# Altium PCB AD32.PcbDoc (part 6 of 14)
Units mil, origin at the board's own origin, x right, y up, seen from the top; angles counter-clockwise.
Board outline 7007.87 x 4368.85 mil, 12 copper layers (Top Layer, Int1 (GND), Int2 (AVDD), Int3 (DVDD), Int4 (GND), Int5 (ST), Int6 (SB), Int8 (AGND), Int7 (AVCC), Int9 (VCCA), Int10 (GND), Bottom Layer), stack 60.136 mil thick; 1350 components, 880 nets, 4712 pads, 2835 vias.
Unrouted connection lines stored in the file: 19.
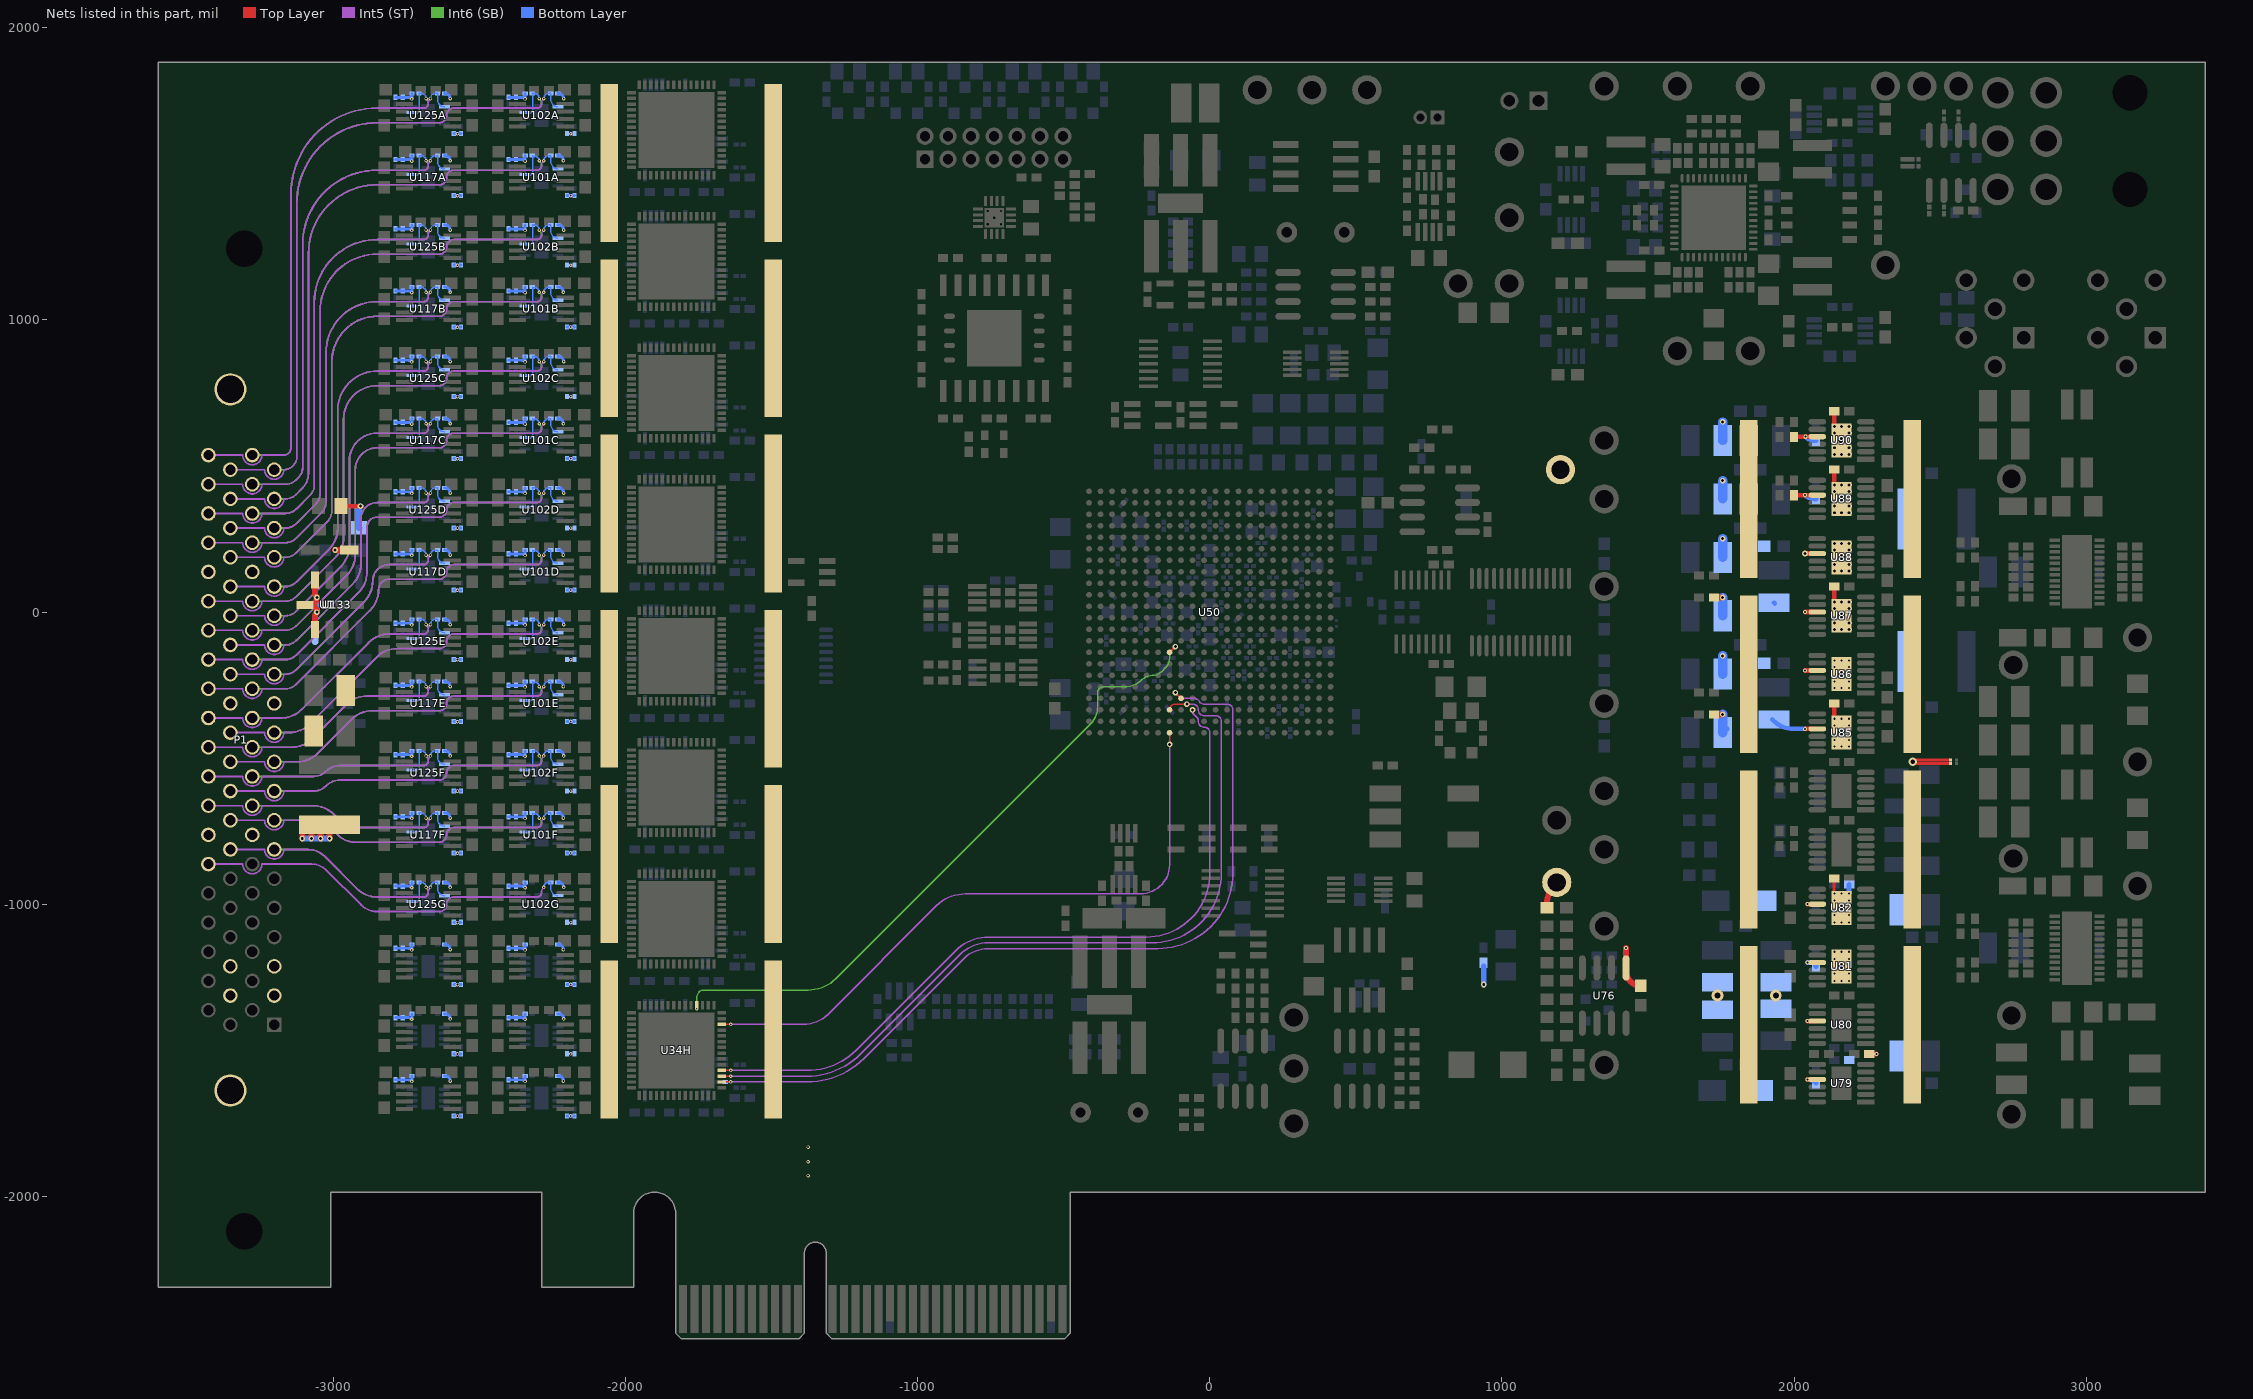
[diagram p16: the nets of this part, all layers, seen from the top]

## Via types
v1: diameter 12, hole 6, Top Layer to Bottom Layer, tented both sides, 1497 vias
v2: diameter 20, hole 10, Top Layer to Bottom Layer, tented both sides, 364 vias
v3: diameter 19, hole 10, Top Layer to Bottom Layer, tented both sides, 347 vias
v4: diameter 14, hole 7, Top Layer to Bottom Layer, tented both sides, 228 vias
v5: diameter 19.68, hole 7.87, Top Layer to Bottom Layer, 225 vias
v6: diameter 19.02, hole 10, Top Layer to Bottom Layer, tented both sides, 85 vias
v7: diameter 20, hole 10, Top Layer to Bottom Layer, 32 vias
v8: diameter 40, hole 20, Top Layer to Bottom Layer, tented both sides, 14 vias
v9: diameter 30, hole 15, Top Layer to Bottom Layer, tented both sides, 12 vias
v10: diameter 25, hole 13, Top Layer to Bottom Layer, 8 vias
v11: diameter 40, hole 20, Top Layer to Bottom Layer, 6 vias
v12: diameter 50, hole 20, Top Layer to Bottom Layer, 6 vias
v13: diameter 66, hole 47, Top Layer to Bottom Layer, tented both sides, 3 vias
v14: diameter 63, hole 45, Top Layer to Bottom Layer, 2 vias
v15: diameter 50, hole 25, Top Layer to Bottom Layer, 2 vias
v16: diameter 12, hole 6, Top Layer to Bottom Layer, 2 vias
v17: diameter 60, hole 40, Top Layer to Bottom Layer, tented both sides, 1 vias
v18: diameter 60, hole 40, Top Layer to Bottom Layer, 1 vias

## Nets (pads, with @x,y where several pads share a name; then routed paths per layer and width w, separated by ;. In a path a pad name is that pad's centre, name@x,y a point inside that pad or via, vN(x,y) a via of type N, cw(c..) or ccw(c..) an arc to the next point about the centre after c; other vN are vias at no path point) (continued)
ADC8.GPIO7: U34H.18 U50.H15 | length 2258.9
  Top Layer w5: U50.H15@-137.8,-137.8 v6(-118.11,-118.11)
  Int6 (SB) w5: v1(-1756.1,-1357.31) -1756.1,-1318.6 cw(c-1731.25,-1318.6) -1731.25,-1293.75 -1374.54,-1293.75 ccw(c-1374.54,-1160.15) -1280.07,-1254.62 -409.51,-384.06 ccw(c-471.45,-322.12) -383.86,-322.12 -383.86,-275.59 cw(c-364.17,-275.59) -364.17,-255.91 -291.9,-255.91 ccw(c-291.9,-169.01) -230.45,-230.45 cw(c-196.85,-264.06) -196.85,-216.54 ccw(c-196.85,-169.01) -163.25,-202.62 -151.71,-191.08 ccw(c-185.32,-157.48) -137.8,-157.48 cw(c-90.27,-157.48) v6@-123.89,-123.89 ; v6@-123.88,-123.88 v6(-118.11,-118.11)
ADC8.ODR: U34H.12 U50.A15 | length 2214.8
  Top Layer w5: U34H.12@-1670.38,-1411.42 v1(-1639.57,-1411.42) ; v6(-137.8,-452.76) U50.A15@-137.8,-413.39
  Int5 (ST) w5: v1(-1639.57,-1411.42) -1391.38,-1411.42 ccw(c-1391.38,-1291.73) -1306.75,-1376.36 -935.77,-1005.39 cw(c-837.22,-1103.94) -837.22,-964.57 -237.8,-964.57 ccw(c-237.8,-864.57) -137.8,-864.57 v6(-137.8,-452.76)
ADC8.SCLK: R417H.1 U34H.2 U50.D14 | length 2895.7
  Top Layer w5: U34H.2@-1670.38,-1608.27 v1(-1639.57,-1608.27) ; v6(-118.11,-275.59) U50.D14@-98.43,-295.28
  Int5 (ST) w5: v1(-1639.57,-1608.27) -1378.87,-1608.27 ccw(c-1378.87,-1331.1) -1182.88,-1527.09 -842.42,-1186.63 cw(c-757.79,-1271.26) -757.79,-1151.57 -178.74,-1151.57 ccw(c-178.74,-894.09) 78.74,-894.09 78.74,-334.65 ccw(c59.06,-334.65) 59.06,-314.96 -19.68,-314.96 cw(c-19.68,-295.28) -36.73,-305.12 ccw(c-53.78,-314.96) -53.78,-295.28 -78.74,-295.28 cw(c-78.74,-247.75) -112.34,-281.37 v6(-118.11,-275.59)
  Bottom Layer w5: R417H.1@-1658.44,-1608.27 v1(-1639.57,-1608.27)
ADC8.SI: U34H.4 U50.C13 | length 2555.9
  Top Layer w5: U34H.4@-1670.38,-1568.9 v1@-1639.53,-1568.9
  Int5 (ST) w5: v1(-1639.57,-1568.9) -1378.87,-1568.9 ccw(c-1378.87,-1331.1) -1210.72,-1499.25 -870.26,-1158.79 cw(c-757.79,-1271.26) -757.79,-1112.2 -218.11,-1112.2 ccw(c-218.11,-894.09) 0,-894.09 0,-413.39 ccw(c-19.68,-413.39) -19.68,-393.7 cw(c-19.68,-374.02) -39.37,-374.02 -39.37,-371.71 ccw(c-52.81,-371.71) -43.31,-362.2 -55.12,-350.39 cw(c-45.61,-340.89) -59.06,-340.89 v6(-59.06,-334.65)
ADC8.SO: U34H.3 U50.C15 | length 2759.8
  Top Layer w5: U34H.3@-1670.38,-1588.58 v1(-1639.57,-1588.58) ; U50.C15@-137.8,-334.65 cw(c-118.11,-334.65) -118.11,-314.96 v6(-78.74,-314.96)
  Int5 (ST) w5: v1(-1639.57,-1588.58) -1378.86,-1588.58 ccw(c-1378.86,-1331.1) -1196.8,-1513.17 -856.34,-1172.71 cw(c-757.79,-1271.26) -757.79,-1131.89 -198.43,-1131.89 ccw(c-198.43,-894.09) 39.37,-894.09 39.37,-374.02 ccw(c19.69,-374.02) 19.69,-354.33 -19.69,-354.33 cw(c-19.69,-334.65) -39.37,-334.65 ccw(c-59.06,-334.65) -59.06,-314.96 v6(-78.74,-314.96)
AGND: C1.1 C2.1 C7.2 C8.2 C63.1 C67.1 C80.1 C81.1 C108.1 C109.2 C112.2 C113.1 C120.2 C121.1 C122.1 C123.1 C128.2 C129.1 C130.1 C131.1 C132.1 C133.1 C134.1 C135.1 C145.1 C384A.1 C384B.1 C384C.1 C384D.1 C384E.1 C384F.1 C384G.1 C384H.1 C385A.1 C385B.1 C385C.1 C385D.1 C385E.1 C385F.1 C385G.1 C385H.1 C400A.2 C400B.2 C400C.2 C400D.2 C400E.2 C400F.2 C400G.2 C400H.2 C401A.2 C401B.2 C401C.2 C401D.2 C401E.2 C401F.2 C401G.2 C401H.2 C416A.1 C416B.1 C416C.1 C416D.1 C416E.1 C416F.1 C416G.1 C416H.1 C424A.1 C424B.1 C424C.1 C424D.1 C424E.1 C424F.1 C424G.1 C424H.1 C432A.2 C432B.2 C432C.2 C432D.2 C432E.2 C432F.2 C432G.2 C432H.2 C440A.2 C440B.2 C440C.2 C440D.2 C440E.2 C440F.2 C440G.2 C440H.2 C448A.1 C448B.1 C448C.1 C448D.1 C448E.1 C448F.1 C448G.1 C448H.1 C449A.1 C449B.1 C449C.1 C449D.1 C449E.1 C449F.1 C449G.1 C449H.1 C464A.2 C464B.2 C464C.2 C464D.2 C464E.2 C464F.2 C464G.2 C464H.2 C465A.2 C465B.2 C465C.2 C465D.2 C465E.2 C465F.2 C465G.2 C465H.2 C480A.2 C480B.2 C480C.2 C480D.2 C480E.2 C480F.2 C480G.2 C480H.2 C488A.1 C488B.1 C488C.1 C488D.1 C488E.1 C488F.1 C488G.1 C488H.1 C496A.1 C496B.1 C496C.1 C496D.1 C496E.1 C496F.1 C496G.1 C496H.1 C504A.2 C504B.2 C504C.2 C504D.2 C504E.2 C504F.2 C504G.2 C504H.2 C512.2 D3.1 D9.1 D10.2 MP1.1 MP1.2 MP2.1 MP2.2 MP3.1 MP3.2 MP4.1 MP4.2 MP5.1 MP5.2 MP6.1 MP6.2 MP7.1 MP7.2 MP8.1 MP8.2 MP9.1 MP9.2 MP10.1 MP10.2 P1.5 P1.6 P1.9 P1.10 P1.27 P1.28 P1.45 P1.46 P1.63 P1.64 P1.81 P1.82 R220.2 R222.2 R231.2 R232.1 R247.2 R248.2 R249.2 R250.2 R252.1 R257.1 R305.2 R307.2 R309.2 R310.1 R312.1 R313.1 R316.2 R317.2 R553A.2 R553B.2 R553C.2 R553D.2 R553E.2 R553F.2 R553G.2 R553H.2 R554A.2 R554B.2 R554C.2 R554D.2 R554E.2 R554F.2 R554G.2 R554H.2 R569A.1 R569B.1 R569C.1 R569D.1 R569E.1 R569F.1 R569G.1 R569H.1 R577A.1 R577B.1 R577C.1 R577D.1 R577E.1 R577F.1 R577G.1 R577H.1 R617A.2 R617B.2 R617C.2 R617D.2 R617E.2 R617F.2 R617G.2 R617H.2 R618A.2 R618B.2 R618C.2 R618D.2 R618E.2 R618F.2 R618G.2 R618H.2 R633A.1 R633B.1 R633C.1 R633D.1 R633E.1 R633F.1 R633G.1 R633H.1 R634A.1 R634B.1 R634C.1 R634D.1 R634E.1 R634F.1 R634G.1 R634H.1 TP13.1 TP15.1 U1.3 U1.4 U1.5 U76.5 U79.9 U80.9 U81.9 U81.13 U82.9 U82.13 U85.9 U85.13 U86.9 U86.13 U87.9 U87.13 U88.9 U88.13 U89.9 U89.13 U90.9 U90.13 U133.4 W1.2 W2.2 | length 6935.6
  Top Layer w10: v4(2045.19,-1199.41) 2079.14,-1199.41 U81.9@2079.44,-1199.7 ; R252.1@2136.91,-912.5 2136.91,-962.5 v4(2137.5,-962.5) ; W1.2@2535,-518.75 2421.34,-518.75 cw(c2421.34,-497.41) v9(2406.25,-512.5) cw(c2421.34,-527.59) 2421.34,-506.25 W2.2@2535,-506.25
  Top Layer w16: C2.1@-2974.11,362.5 v3(-2906.94,362.5) ; R316.2@2000,399.41 cw(c2000.89,399.41) 2000.89,400.3 v4(2037.5,400.3) ; R317.2@2000,599.41 cw(c2000.89,599.41) 2000.89,600.3 v4(2038.19,600.3) U90.9@2079.44,600.3 ; v4@2037.05,400.29 cw(c2037.5,384.3) v4(2037.5,400.3) ; v4(2037.5,-399.7) U85.9@2079.44,-399.7 ; v4(2037.5,-200) 2037.8,-199.7 U86.9@2079.44,-199.7 ; v4(2037.5,0.3) U87.9@2079.44,0.3 ; v2(2037.5,200) 2037.8,200.3 U88.9@2079.44,200.3 ; v4(2045.19,-1599.7) U79.9@2079.44,-1599.7 ; v4(2045.19,-1400) 2079.14,-1400 U80.9@2079.44,-1399.7 ; v4(2045.19,-999.7) U82.9@2079.44,-999.7 ; U89.9@2079.44,400.3 v4(2037.5,400.3) ; U85.13@2136.91,-364.41 R247.2@2136.91,-312.5 ; U87.13@2136.91,34.86 R248.2@2136.91,87.5 ; U89.13@2136.91,434.34 R249.2@2136.91,487.5 ; U90.13@2136.91,633.91 R250.2@2136.91,687.5 ; R257.1@2256.84,-1512.5 v4(2281.25,-1512.5)
  Top Layer w20: v3(-3106.25,-775) -3106.25,-727.36 C1.1@-3075,-727.36 ; U1.4@-3097.15,25 U1.4@-3081.25,25 ; v3(-3075,-775) C1.1@-3075,-727.36 ; U1.5@-3062.5,-59.65 -3062.5,-15.09 cw(c-3041.16,-15.09) v3(-3056.25,0) ccw(c-3081.25,0) U1.4@-3081.25,25 ; U1.3@-3062.5,109.65 -3062.5,65.09 ccw(c-3041.16,65.09) v3(-3056.25,50) cw(c-3081.25,50) U1.4@-3081.25,25 ; v3(-3043.75,-775) C1.1@-3043.75,-727.36 ; v3(-3012.5,-775) C1.1@-3012.5,-727.36 C1.1@-3043.75,-727.36 ; v3(-2993.69,212.5) D3.1@-2945.57,212.5 ; C63.1@1154.04,-1012.5 1154.04,-999.89 cw(c1254.04,-999.89) 1183.32,-929.18 TP13.1@1187.5,-925 ; v4(1425,-1150) U76.5@1425,-1218.01 1425,-1229.04 ccw(c1475,-1229.04) C67.1@1475,-1279.04 ; R220.2@1725.59,-350 v6(1755.12,-350) ; R222.2@1725.59,50 v6(1755.12,50) ; C1.1@-3075,-727.36 C1.1@-3043.75,-727.36
  Bottom Layer w10: C464H.2@-2787.5,-1600.56 C496H.1@-2762.5,-1600.56 -2744.98,-1600.56 cw(c-2744.98,-1619.98) v1(-2731.25,-1606.25) -2731.25,-1588.86 cw(c-2729.33,-1588.86) R633H.1@-2730.69,-1587.5 ; C465H.2@-2787.5,-1388.06 C488H.1@-2762.5,-1388.06 -2744.98,-1388.06 cw(c-2744.98,-1407.48) v1(-2731.25,-1393.75) ccw(c-2732.61,-1392.39) -2730.69,-1392.39 R634H.1@-2730.69,-1375 ; C464G.2@-2787.5,-1150.56 C496G.1@-2762.5,-1150.56 -2744.98,-1150.56 cw(c-2744.98,-1169.98) v1(-2731.25,-1156.25) -2731.25,-1138.86 cw(c-2729.33,-1138.86) R633G.1@-2730.69,-1137.5 ; C465G.2@-2787.5,-938.06 C488G.1@-2762.5,-938.06 -2744.98,-938.06 cw(c-2744.98,-957.48) v1(-2731.25,-943.75) ccw(c-2732.61,-942.39) -2730.69,-942.39 R634G.1@-2730.69,-925 ; C464F.2@-2787.5,-700.56 C496F.1@-2762.5,-700.56 -2744.98,-700.56 cw(c-2744.98,-719.98) v1(-2731.25,-706.25) -2731.25,-688.86 cw(c-2729.33,-688.86) R633F.1@-2730.69,-687.5 ; C465F.2@-2787.5,-488.06 C488F.1@-2762.5,-488.06 -2744.98,-488.06 cw(c-2744.98,-507.48) v1(-2731.25,-493.75) ccw(c-2732.61,-492.39) -2730.69,-492.39 R634F.1@-2730.69,-475 ; C464E.2@-2787.5,-250.56 C496E.1@-2762.5,-250.56 -2744.98,-250.56 cw(c-2744.98,-269.98) v1(-2731.25,-256.25) -2731.25,-238.86 cw(c-2729.33,-238.86) R633E.1@-2730.69,-237.5 ; C465E.2@-2787.5,-38.06 C488E.1@-2762.5,-38.06 -2744.98,-38.06 cw(c-2744.98,-57.48) v1(-2731.25,-43.75) ccw(c-2732.61,-42.39) -2730.69,-42.39 R634E.1@-2730.69,-25 ; C464D.2@-2787.5,199.44 C496D.1@-2762.5,199.44 -2744.98,199.44 cw(c-2744.98,180.02) v1(-2731.25,193.75) -2731.25,211.14 cw(c-2729.33,211.14) R633D.1@-2730.69,212.5 ; C465D.2@-2787.5,411.94 C488D.1@-2762.5,411.94 -2744.98,411.94 cw(c-2744.98,392.52) v1(-2731.25,406.25) ccw(c-2732.61,407.61) -2730.69,407.61 R634D.1@-2730.69,425 ; C464C.2@-2787.5,649.44 C496C.1@-2762.5,649.44 -2744.98,649.44 cw(c-2744.98,630.02) v1(-2731.25,643.75) -2731.25,661.14 cw(c-2729.33,661.14) R633C.1@-2730.69,662.5 ; C465C.2@-2787.5,861.94 C488C.1@-2762.5,861.94 -2744.98,861.94 cw(c-2744.98,842.52) v1(-2731.25,856.25) ccw(c-2732.61,857.61) -2730.69,857.61 R634C.1@-2730.69,875 ; C464B.2@-2787.5,1099.44 C496B.1@-2762.5,1099.44 -2744.98,1099.44 cw(c-2744.98,1080.02) v1(-2731.25,1093.75) -2731.25,1111.14 cw(c-2729.33,1111.14) R633B.1@-2730.69,1112.5 ; C465B.2@-2787.5,1311.94 C488B.1@-2762.5,1311.94 -2744.98,1311.94 cw(c-2744.98,1292.52) v1(-2731.25,1306.25) ccw(c-2732.61,1307.61) -2730.69,1307.61 R634B.1@-2730.69,1325 ; C464A.2@-2787.5,1549.44 C496A.1@-2762.5,1549.44 -2744.98,1549.44 cw(c-2744.98,1530.02) v1(-2731.25,1543.75) -2731.25,1561.14 cw(c-2729.33,1561.14) R633A.1@-2730.69,1562.5 ; C465A.2@-2787.5,1761.94 C488A.1@-2762.5,1761.94 -2744.98,1761.94 cw(c-2744.98,1742.52) v1(-2731.25,1756.25) ccw(c-2732.61,1757.61) -2730.69,1757.61 R634A.1@-2730.69,1775 ; R617H.2@-2619.31,-1587.5 -2617.5,-1587.5 cw(c-2617.5,-1605) v1(-2600,-1605) ; R618H.2@-2619.31,-1375 -2617.5,-1375 cw(c-2617.5,-1392.5) v1(-2600,-1392.5) ; R617G.2@-2619.31,-1137.5 -2617.5,-1137.5 cw(c-2617.5,-1155) v1(-2600,-1155) ; R618G.2@-2619.31,-925 -2617.5,-925 cw(c-2617.5,-942.5) v1(-2600,-942.5) ; R617F.2@-2619.31,-687.5 -2617.5,-687.5 cw(c-2617.5,-705) v1(-2600,-705) ; R618F.2@-2619.31,-475 -2617.5,-475 cw(c-2617.5,-492.5) v1(-2600,-492.5) ; R617E.2@-2619.31,-237.5 -2617.5,-237.5 cw(c-2617.5,-255) v1(-2600,-255) ; R618E.2@-2619.31,-25 -2617.5,-25 cw(c-2617.5,-42.5) v1(-2600,-42.5) ; R617D.2@-2619.31,212.5 -2617.5,212.5 cw(c-2617.5,195) v1(-2600,195) ; R618D.2@-2619.31,425 -2617.5,425 cw(c-2617.5,407.5) v1(-2600,407.5) ; R617C.2@-2619.31,662.5 -2617.5,662.5 cw(c-2617.5,645) v1(-2600,645) ; R618C.2@-2619.31,875 -2617.5,875 cw(c-2617.5,857.5) v1(-2600,857.5) ; R617B.2@-2619.31,1112.5 -2617.5,1112.5 cw(c-2617.5,1095) v1(-2600,1095) ; R618B.2@-2619.31,1325 -2617.5,1325 cw(c-2617.5,1307.5) v1(-2600,1307.5) ; R617A.2@-2619.31,1562.5 -2617.5,1562.5 cw(c-2617.5,1545) v1(-2600,1545) ; R618A.2@-2619.31,1775 -2617.5,1775 cw(c-2617.5,1757.5) v1(-2600,1757.5) ; C480H.2@-2587.5,-1724.44 C448H.1@-2562.5,-1724.44 ; C449H.1@-2587.5,-1511.94 C504H.2@-2562.5,-1511.94 ; C480G.2@-2587.5,-1274.44 C448G.1@-2562.5,-1274.44 ; C449G.1@-2587.5,-1061.94 C504G.2@-2562.5,-1061.94 ; C480F.2@-2587.5,-824.44 C448F.1@-2562.5,-824.44 ; C449F.1@-2587.5,-611.94 C504F.2@-2562.5,-611.94 ; C480E.2@-2587.5,-374.44 C448E.1@-2562.5,-374.44 ; C449E.1@-2587.5,-161.94 C504E.2@-2562.5,-161.94 ; C480D.2@-2587.5,75.56 C448D.1@-2562.5,75.56 ; C449D.1@-2587.5,288.06 C504D.2@-2562.5,288.06 ; C480C.2@-2587.5,525.56 C448C.1@-2562.5,525.56 ; C449C.1@-2587.5,738.06 C504C.2@-2562.5,738.06 ; C480B.2@-2587.5,975.56 C448B.1@-2562.5,975.56 ; C449B.1@-2587.5,1188.06 C504B.2@-2562.5,1188.06 ; C480A.2@-2587.5,1425.56 C448A.1@-2562.5,1425.56 ; C449A.1@-2587.5,1638.06 C504A.2@-2562.5,1638.06 ; C400H.2@-2400,-1600.56 C424H.1@-2375,-1600.56 -2357.48,-1600.56 cw(c-2357.48,-1619.98) v1(-2343.75,-1606.25) -2343.75,-1588.64 cw(c-2342.14,-1588.64) R577H.1@-2343.28,-1587.5 ; C401H.2@-2400,-1388.06 C416H.1@-2375,-1388.06 -2357.48,-1388.06 cw(c-2357.48,-1407.48) v1(-2343.75,-1393.75) -2343.75,-1376.36 cw(c-2341.83,-1376.36) R569H.1@-2343.19,-1375 ; C400G.2@-2400,-1150.56 C424G.1@-2375,-1150.56 -2357.48,-1150.56 cw(c-2357.48,-1169.98) v1(-2343.75,-1156.25) -2343.75,-1138.64 cw(c-2342.14,-1138.64) R577G.1@-2343.28,-1137.5 ; C401G.2@-2400,-938.06 C416G.1@-2375,-938.06 -2357.48,-938.06 cw(c-2357.48,-957.48) v1(-2343.75,-943.75) -2343.75,-926.36 cw(c-2341.83,-926.36) R569G.1@-2343.19,-925 ; C400F.2@-2400,-700.56 C424F.1@-2375,-700.56 -2357.48,-700.56 cw(c-2357.48,-719.98) v1(-2343.75,-706.25) -2343.75,-688.64 cw(c-2342.14,-688.64) R577F.1@-2343.28,-687.5 ; C401F.2@-2400,-488.06 C416F.1@-2375,-488.06 -2357.48,-488.06 cw(c-2357.48,-507.48) v1(-2343.75,-493.75) -2343.75,-476.36 cw(c-2341.83,-476.36) R569F.1@-2343.19,-475 ; C400E.2@-2400,-250.56 C424E.1@-2375,-250.56 -2357.48,-250.56 cw(c-2357.48,-269.98) v1(-2343.75,-256.25) -2343.75,-238.64 cw(c-2342.14,-238.64) R577E.1@-2343.28,-237.5 ; C401E.2@-2400,-38.06 C416E.1@-2375,-38.06 -2357.48,-38.06 cw(c-2357.48,-57.48) v1(-2343.75,-43.75) -2343.75,-26.36 cw(c-2341.83,-26.36) R569E.1@-2343.19,-25 ; C400D.2@-2400,199.44 C424D.1@-2375,199.44 -2357.48,199.44 cw(c-2357.48,180.02) v1(-2343.75,193.75) -2343.75,211.36 cw(c-2342.14,211.36) R577D.1@-2343.28,212.5 ; C401D.2@-2400,411.94 C416D.1@-2375,411.94 -2357.48,411.94 cw(c-2357.48,392.52) v1(-2343.75,406.25) -2343.75,423.64 cw(c-2341.83,423.64) R569D.1@-2343.19,425 ; C400C.2@-2400,649.44 C424C.1@-2375,649.44 -2357.48,649.44 cw(c-2357.48,630.02) v1(-2343.75,643.75) -2343.75,661.36 cw(c-2342.14,661.36) R577C.1@-2343.28,662.5 ; C401C.2@-2400,861.94 C416C.1@-2375,861.94 -2357.48,861.94 cw(c-2357.48,842.52) v1(-2343.75,856.25) -2343.75,873.64 cw(c-2341.83,873.64) R569C.1@-2343.19,875 ; C400B.2@-2400,1099.44 C424B.1@-2375,1099.44 -2357.48,1099.44 cw(c-2357.48,1080.02) v1(-2343.75,1093.75) -2343.75,1111.36 cw(c-2342.14,1111.36) R577B.1@-2343.28,1112.5 ; C401B.2@-2400,1311.94 C416B.1@-2375,1311.94 -2357.48,1311.94 cw(c-2357.48,1292.52) v1(-2343.75,1306.25) -2343.75,1323.64 cw(c-2341.83,1323.64) R569B.1@-2343.19,1325 ; C400A.2@-2400,1549.44 C424A.1@-2375,1549.44 -2357.48,1549.44 cw(c-2357.48,1530.02) v1(-2343.75,1543.75) -2343.75,1561.36 cw(c-2342.14,1561.36) R577A.1@-2343.28,1562.5 ; C401A.2@-2400,1761.94 C416A.1@-2375,1761.94 -2357.48,1761.94 cw(c-2357.48,1742.52) v1(-2343.75,1756.25) -2343.75,1773.64 cw(c-2341.83,1773.64) R569A.1@-2343.19,1775 ; R553H.2@-2231.81,-1587.5 -2230,-1587.5 cw(c-2230,-1605) v1(-2212.5,-1605) ; R554H.2@-2231.81,-1375 -2229,-1375 cw(c-2229,-1392.5) v1(-2211.5,-1392.5) ; R553G.2@-2231.81,-1137.5 -2230,-1137.5 cw(c-2230,-1155) v1(-2212.5,-1155) ; R554G.2@-2231.81,-925 -2229,-925 cw(c-2229,-942.5) v1(-2211.5,-942.5) ; R553F.2@-2231.81,-687.5 -2230,-687.5 cw(c-2230,-705) v1(-2212.5,-705) ; R554F.2@-2231.81,-475 -2229,-475 cw(c-2229,-492.5) v1(-2211.5,-492.5) ; R553E.2@-2231.81,-237.5 -2230,-237.5 cw(c-2230,-255) v1(-2212.5,-255) ; R554E.2@-2231.81,-25 -2229,-25 cw(c-2229,-42.5) v1(-2211.5,-42.5) ; R553D.2@-2231.81,212.5 -2230,212.5 cw(c-2230,195) v1(-2212.5,195) ; R554D.2@-2231.81,425 -2229,425 cw(c-2229,407.5) v1(-2211.5,407.5) ; R553C.2@-2231.81,662.5 -2230,662.5 cw(c-2230,645) v1(-2212.5,645) ; R554C.2@-2231.81,875 -2229,875 cw(c-2229,857.5) v1(-2211.5,857.5) ; R553B.2@-2231.81,1112.5 -2230,1112.5 cw(c-2230,1095) v1(-2212.5,1095) ; R554B.2@-2231.81,1325 -2229,1325 cw(c-2229,1307.5) v1(-2211.5,1307.5) ; R553A.2@-2231.81,1562.5 -2230,1562.5 cw(c-2230,1545) v1(-2212.5,1545) ; R554A.2@-2231.81,1775 -2229,1775 cw(c-2229,1757.5) v1(-2211.5,1757.5) ; C440H.2@-2200,-1724.44 C384H.1@-2175,-1724.44 ; C440G.2@-2200,-1274.44 C384G.1@-2175,-1274.44 ; C440F.2@-2200,-824.44 C384F.1@-2175,-824.44 ; C440E.2@-2200,-374.44 C384E.1@-2175,-374.44 ; C440D.2@-2200,75.56 C384D.1@-2175,75.56 ; C440C.2@-2200,525.56 C384C.1@-2175,525.56 ; C440B.2@-2200,975.56 C384B.1@-2175,975.56 ; C440A.2@-2200,1425.56 C384A.1@-2175,1425.56
  Bottom Layer w16: C122.1@1925,-367.62 1927.8,-370.42 ccw(c1998.51,-299.7) 1998.51,-399.7 v4(2037.5,-399.7) ; C123.1@1931.25,32.38 C123.1@1934.05,29.58 ; v4(2037.5,400.3) ccw(c2069.82,432.61) 2069.82,386.91 R312.1@2075,386.91 ; v4(2038.19,600.3) ccw(c2070.51,632.61) 2070.51,586.91 R313.1@2075,586.91 ; v4(2045.19,-1599.7) cw(c2045.19,-1639.35) 2073.22,-1611.32 R309.2@2075,-1613.09 ; v4(2045.19,-1199.41) 2061.32,-1199.41 cw(c2061.32,-1213.09) R310.1@2075,-1213.09 R310.1@2072.72,-1210.81 ; v2@2136.91,436.43 ccw(c2138.93,436.43) v2(2137.5,435) ; v4(2187.5,-962.5) 2187.5,-933.93 cw(c2189.52,-933.93) R307.2@2188.09,-932.5
  Bottom Layer w20: v3(-3106.25,-775) v3(-3075,-775) v3(-3043.75,-775) v3(-3012.5,-775) ; v3(-3056.25,0) v3(-3056.25,50) ; C512.2@-2910.36,287.5 cw(c-2910.36,290.52) C512.2@-2912.5,288.39 -2912.5,356.94 cw(c-2906.94,356.94) v3(-2906.94,362.5) ; v2(937.5,-1275) C145.1@937.5,-1213.39 ; C130.1@1755.12,-412.5 C130.1@1767.91,-399.7
  Bottom Layer w31.89: C130.1@1755.12,-412.5 v6(1755.12,-350) ; C135.1@1755.12,587.5 v6(1755.12,650.85)
  Bottom Layer w31.97: C131.1@1755.12,-212.5 v6(1755.12,-149.9) ; C132.1@1755.12,-12.5 v6(1755.12,50) ; C133.1@1755.12,187.5 v6(1755.12,251.48) ; C134.1@1755.12,387.5 v6(1755.12,450)
  other v1: -1375,-1928.75 -1375,-1881.25 -1375,-1831.25 -2575,-1725 -2187.5,-1724.44 -2575,-1512.5 -2187.5,-1512.5 -2575,-1275 -2187.5,-1274.44 -2575,-1062.5 -2187.5,-1062.5 -2575,-825 -2187.5,-824.44 -2575,-612.5 -2187.5,-612.5 -2575,-375 -2187.5,-374.44 -2575,-162.5 -2187.5,-162.5 -2575,75 -2187.5,75.56 -2575,287.5 -2187.5,287.5 -2575,525 -2187.5,525.56 -2575,737.5 -2187.5,737.5 -2575,975 -2187.5,975.56 -2575,1187.5 -2187.5,1187.5 -2575,1425 -2187.5,1425.56 -2575,1637.5 -2187.5,1637.5
  other v2: 2137.5,-60 2162.5,-60 2187.5,-60 2137.5,-37.5 2187.5,-37.5 2137.5,12.5 2187.5,12.5 2137.5,35 2162.5,35 2187.5,35 2137.5,140 2162.5,140 2187.5,140 2137.5,162.5 2187.5,162.5 2137.5,212.5 2187.5,212.5 2137.5,235 2162.5,235 2187.5,235 2137.5,340 2162.5,340 2187.5,340 2137.5,362.5 2187.5,362.5 2137.5,412.5 2187.5,412.5 2162.5,435 2187.5,435 2137.5,540 2162.5,540 2187.5,540 2137.5,562.5 2187.5,562.5 2137.5,612.5 2187.5,612.5 2137.5,635 2162.5,635 2187.5,635
  other v4: 2137.5,-1262.5 2162.5,-1262.5 2187.5,-1262.5 2137.5,-1237.5 2187.5,-1237.5 2137.5,-1187.5 2187.5,-1187.5 2137.5,-1162.5 2162.5,-1162.5 2187.5,-1162.5 2137.5,-1062.5 2162.5,-1062.5 2187.5,-1062.5 2137.5,-1037.5 2187.5,-1037.5 2137.5,-987.5 2187.5,-987.5 2162.5,-962.5 2137.5,-460 2162.5,-460 2187.5,-460 2137.5,-437.5 2187.5,-437.5 2137.5,-387.5 2187.5,-387.5 2137.5,-365 2162.5,-365 2187.5,-365 2137.5,-260 2162.5,-260 2187.5,-260 2137.5,-237.5 2187.5,-237.5 2137.5,-187.5 2187.5,-187.5 2137.5,-165 2162.5,-165 2187.5,-165
  other v8: 1737.5,-1312.5 1937.5,-1312.5
  other v11: 2162.5,-1212.5 2162.5,-1012.5
  other v12: 2162.5,-412.5 2162.5,-212.5 2162.5,-12.5 2162.5,187.5 2162.5,387.5 2162.5,587.5
ANALOG1.A1_N: P1.80 R618A.1 U125A.5 | length 1962.3
  Int5 (ST) w6: P1.80@-3427.3,537.5 -3310.3,537.5 ccw(c-3277.3,537.5) -3244.3,537.5 -3201.22,537.5 -3169.3,537.5 ccw(c-3169.3,561.8) -3145,561.8 -3145,1430 cw(c-2850,1430) -2850,1725 -2690,1725 ccw(c-2690,1740) -2675,1740 cw(c-2650.86,1740) -2667.93,1757.07 v1(-2667.5,1757.5)
  Bottom Layer w5: v1(-2667.5,1757.5) cw(c-2650,1757.5) -2650,1775 R618A.1@-2643.19,1775 -2643.19,1753.69 ccw(c-2618.89,1753.69) U125A.5@-2618.89,1729.4
ANALOG1.A1_P: P1.79 R634A.2 U125A.3 | length 1803.9
  Int6 (SB) w6: P1.79@-3277.3,537.5 -3169.3,537.5 ccw(c-3169.3,561.8) -3145,561.8 -3145,1430.36 cw(c-2850.36,1430.36) -2850.36,1725 -2690,1725 ccw(c-2690,1740) -2675,1740 ccw(c-2699.14,1740) -2682.07,1757.07 v1(-2682.5,1757.5)
  Bottom Layer w5: U125A.3@-2731.1,1709.72 -2714.03,1709.72 ccw(c-2714.03,1718.75) -2705,1718.75 -2705,1773.19 ccw(c-2706.81,1773.19) R634A.2@-2706.81,1775 -2700,1775 cw(c-2700,1757.5) v1(-2682.5,1757.5)
ANALOG1.A2_N: P1.78 R554A.1 U102A.5 | length 2301.9
  Int5 (ST) w6: P1.78@-3352.3,487.5 -3235.3,487.5 ccw(c-3202.3,487.5) -3169.3,487.5 ccw(c-3169.3,531.8) -3125,531.8 -3125,1398.64 ; -3125,1400 cw(c-2850,1400) -2850,1675 -2637.5,1675 ccw(c-2637.5,1700) -2612.5,1700 cw(c-2587.5,1700) -2587.5,1725 -2302.5,1725 ccw(c-2302.5,1740) -2287.5,1740 cw(c-2263.36,1740) -2280.43,1757.07 v1(-2280,1757.5)
  Bottom Layer w5: v1(-2280,1757.5) cw(c-2262.5,1757.5) -2262.5,1775 R554A.1@-2255.69,1775 -2255.69,1753.82 ccw(c-2231.39,1753.82) U102A.5@-2231.39,1729.53
ANALOG1.A2_P: P1.77 R569A.2 U102A.3 | length 2144.2
  Int6 (SB) w6: P1.77@-3202.3,487.5 -3169.3,487.5 ccw(c-3169.3,531.8) -3125,531.8 -3125,1398.64 cw(c-2848.64,1398.64) -2848.64,1675 -2637.37,1675 ccw(c-2637.37,1699.87) -2612.5,1699.87 -2612.5,1700 cw(c-2587.5,1700) -2587.5,1725 -2302.5,1725 ccw(c-2302.5,1740) -2287.5,1740 ccw(c-2311.64,1740) -2294.57,1757.07 v1(-2295,1757.5)
  Bottom Layer w5: U102A.3@-2343.6,1709.84 -2326.41,1709.84 ccw(c-2326.41,1718.75) -2317.5,1718.75 -2317.5,1773.19 ccw(c-2319.31,1773.19) R569A.2@-2319.31,1775 -2312.5,1775 cw(c-2312.5,1757.5) v1(-2295,1757.5)
ANALOG1.A3_N: P1.76 R617A.1 U117A.5 | length 1851.1
  Int5 (ST) w6: P1.76@-3427.3,437.5 -3310.3,437.5 ccw(c-3277.3,437.5) -3244.3,437.5 -3163.7,437.5 ccw(c-3163.7,488.68) -3127.51,452.49 -3119.14,460.86 ccw(c-3153.28,495) -3105,495 -3105,1257.5 cw(c-2850,1257.5) -2850,1512.5 -2690,1512.5 ccw(c-2690,1527.5) -2675,1527.5 cw(c-2650.86,1527.5) -2667.93,1544.57 v1(-2667.5,1545)
  Bottom Layer w5: v1(-2667.5,1545) cw(c-2650,1545) -2650,1562.5 R617A.1@-2643.19,1562.5 -2643.19,1541.32 ccw(c-2618.89,1541.32) U117A.5@-2618.89,1517.03
ANALOG1.A3_P: P1.75 R633A.2 U117A.3 | length 1692
  Int6 (SB) w6: P1.75@-3277.3,437.5 -3163.71,437.5 ccw(c-3163.71,488.71) -3127.51,452.49 -3119.14,460.86 ccw(c-3153.28,495) -3105,495 -3105,1257.5 cw(c-2850,1257.5) -2850,1512.5 -2690,1512.5 ccw(c-2690,1527.5) -2675,1527.5 ccw(c-2699.14,1527.5) -2682.07,1544.57 v1(-2682.5,1545)
  Bottom Layer w5: U117A.3@-2731.1,1497.34 -2713.91,1497.34 ccw(c-2713.91,1506.25) -2705,1506.25 -2705,1558.12 ccw(c-2711.19,1558.12) R633A.2@-2706.81,1562.5 -2700,1562.5 cw(c-2700,1545) v1(-2682.5,1545)
ANALOG1.A4_N: P1.74 R553A.1 U101A.5 | length 2187.9
  Int5 (ST) w6: P1.74@-3352.3,387.5 -3235.3,387.5 ccw(c-3202.3,387.5) -3169.3,387.5 -3163.7,387.5 ccw(c-3163.7,438.68) -3127.51,402.49 -3106.21,423.79 ccw(c-3157.43,475) -3085,475 -3085,1227.54 cw(c-2850.04,1227.54) -2850.04,1462.5 -2637.5,1462.5 ccw(c-2637.5,1487.5) -2612.5,1487.5 cw(c-2587.5,1487.5) -2587.5,1512.5 -2302.5,1512.5 ccw(c-2302.5,1527.5) -2287.5,1527.5 cw(c-2263.36,1527.5) -2280.43,1544.57 v1(-2280,1545)
  Bottom Layer w5: v1(-2280,1545) cw(c-2262.5,1545) -2262.5,1562.5 R553A.1@-2255.69,1562.5 -2255.69,1541.32 ccw(c-2231.39,1541.32) U101A.5@-2231.39,1517.03
ANALOG1.A4_P: P1.73 R577A.2 U101A.3 | length 2026.6
  Int6 (SB) w6: P1.73@-3202.3,387.5 -3163.71,387.5 ccw(c-3163.71,438.71) -3127.51,402.49 -3106.21,423.79 ccw(c-3157.43,475) -3085,475 -3085,1227.6 cw(c-2850.1,1227.6) -2850.1,1462.5 -2637.5,1462.5 ccw(c-2637.5,1487.5) -2612.5,1487.5 cw(c-2587.5,1487.5) -2587.5,1512.5 -2302.5,1512.5 ccw(c-2302.5,1527.5) -2287.5,1527.5 ccw(c-2311.64,1527.5) -2294.57,1544.57 v1(-2295,1545)
  Bottom Layer w5: U101A.3@-2343.6,1497.34 -2326.41,1497.34 ccw(c-2326.41,1506.25) -2317.5,1506.25 R577A.2@-2317.5,1560.59 ; R577A.2@-2319.41,1562.5 cw(c-2319.41,1560.59) R577A.2@-2317.5,1560.59 ; v1(-2295,1545) ccw(c-2310.59,1545) -2310.59,1560.59 R577A.2@-2317.5,1560.59
ANALOG1.A5_N: P1.72 R618B.1 U125B.5 | length 1707.4
  Int5 (ST) w6: P1.72@-3427.3,337.5 -3310.3,337.5 ccw(c-3277.3,337.5) -3244.3,337.5 -3163.71,337.5 ccw(c-3163.71,388.71) -3127.51,352.49 -3079.14,400.86 ccw(c-3113.28,435) -3065,435 -3065,1060 cw(c-2850,1060) -2850,1275 -2690,1275 ccw(c-2690,1290) -2675,1290 cw(c-2650.86,1290) -2667.93,1307.07 v1(-2667.5,1307.5)
  Bottom Layer w5: v1(-2667.5,1307.5) cw(c-2650,1307.5) -2650,1325 R618B.1@-2643.19,1325 -2643.19,1303.69 ccw(c-2618.89,1303.69) U125B.5@-2618.89,1279.4
ANALOG1.A5_P: P1.71 R634B.2 U125B.3 | length 1548.8
  Int6 (SB) w6: P1.71@-3277.3,337.5 -3163.71,337.5 ccw(c-3163.71,388.71) -3127.51,352.49 -3079.14,400.86 ccw(c-3113.28,435) -3065,435 -3065,1060 cw(c-2850,1060) -2850,1275 -2690,1275 ccw(c-2690,1290) -2675,1290 ccw(c-2699.14,1290) -2682.07,1307.07 v1(-2682.5,1307.5)
  Bottom Layer w5: U125B.3@-2731.1,1259.72 -2714.03,1259.72 ccw(c-2714.03,1268.75) -2705,1268.75 -2705,1323.19 ccw(c-2706.81,1323.19) R634B.2@-2706.81,1325 -2700,1325 cw(c-2700,1307.5) v1(-2682.5,1307.5)
ANALOG1.A6_N: P1.70 R554B.1 U102B.5 | length 2044.9
  Int5 (ST) w6: P1.70@-3352.3,287.5 -3235.3,287.5 ccw(c-3202.3,287.5) -3169.3,287.5 -3163.7,287.5 ccw(c-3163.7,338.68) -3127.51,302.49 -3060.91,369.09 ccw(c-3099.32,407.5) -3045,407.5 -3045,1030 cw(c-2850,1030) -2850,1225 -2637.5,1225 ccw(c-2637.5,1250) -2612.5,1250 cw(c-2587.5,1250) -2587.5,1275 -2302.5,1275 ccw(c-2302.5,1290) -2287.5,1290 cw(c-2263.36,1290) -2280.43,1307.07 v1(-2280,1307.5)
  Bottom Layer w5: v1(-2280,1307.5) cw(c-2262.5,1307.5) -2262.5,1325 R554B.1@-2255.69,1325 -2255.69,1303.82 ccw(c-2231.39,1303.82) U102B.5@-2231.39,1279.53
ANALOG1.A6_P: P1.69 R569B.2 U102B.3 | length 1886.5
  Int6 (SB) w6: P1.69@-3202.3,287.5 -3169.3,287.5 -3163.71,287.5 ccw(c-3163.71,338.71) -3127.51,302.49 -3060.91,369.09 ccw(c-3099.32,407.5) -3045,407.5 -3045,1030 cw(c-2850,1030) -2850,1225 -2637.37,1225 ccw(c-2637.37,1249.87) -2612.5,1249.87 -2612.5,1250 cw(c-2587.5,1250) -2587.5,1275 -2302.5,1275 ccw(c-2302.5,1290) -2287.5,1290 ccw(c-2311.64,1290) -2294.57,1307.07 v1(-2295,1307.5)
  Bottom Layer w5: U102B.3@-2343.6,1259.84 -2326.41,1259.84 ccw(c-2326.41,1268.75) -2317.5,1268.75 -2317.5,1323.19 ccw(c-2319.31,1323.19) R569B.2@-2319.31,1325 -2312.5,1325 cw(c-2312.5,1307.5) v1(-2295,1307.5)
ANALOG1.A7_N: P1.68 R617B.1 U117B.5 | length 1588.3
  Int5 (ST) w6: P1.68@-3427.3,237.5 -3310.3,237.5 ccw(c-3277.3,237.5) -3244.3,237.5 -3163.7,237.5 ccw(c-3163.7,288.68) -3127.51,252.49 -3040.91,339.09 ccw(c-3079.32,377.5) -3025,377.5 -3025,887.5 cw(c-2850,887.5) -2850,1062.5 -2690,1062.5 ccw(c-2690,1077.5) -2675,1077.5 cw(c-2650.86,1077.5) -2667.93,1094.57 v1(-2667.5,1095)
  Bottom Layer w5: v1(-2667.5,1095) cw(c-2650,1095) -2650,1112.5 R617B.1@-2643.19,1112.5 -2643.19,1091.32 ccw(c-2618.89,1091.32) U117B.5@-2618.89,1067.03
ANALOG1.A7_P: P1.67 R633B.2 U117B.3 | length 1429
  Int6 (SB) w6: P1.67@-3277.3,237.5 -3163.71,237.5 ccw(c-3163.71,288.71) -3127.51,252.49 -3040.91,339.09 ccw(c-3079.32,377.5) -3025,377.5 -3025,887.5 ; -3025,887.76 cw(c-2850.26,887.76) -2850.26,1062.5 -2690,1062.5 ccw(c-2690,1077.5) -2675,1077.5 ccw(c-2699.14,1077.5) -2682.07,1094.57 v1(-2682.5,1095)
  Bottom Layer w5: U117B.3@-2731.1,1047.34 -2713.91,1047.34 ccw(c-2713.91,1056.25) -2705,1056.25 -2705,1108.12 ccw(c-2711.19,1108.12) R633B.2@-2706.81,1112.5 -2700,1112.5 cw(c-2700,1095) v1(-2682.5,1095)
ANALOG1.A8_N: P1.66 R553B.1 U101B.5 | length 1925.8
  Int5 (ST) w6: P1.66@-3352.3,187.5 -3235.3,187.5 ccw(c-3202.3,187.5) -3202.3,154.5 ccw(c-3202.3,187.5) -3169.3,187.5 -3163.7,187.5 ccw(c-3163.7,238.68) -3127.51,202.49 -3020.91,309.09 ccw(c-3059.32,347.5) -3005,347.5 -3005,856.74 ; -3005,856.84 cw(c-2849.34,856.84) -2849.59,1012.5 -2637.5,1012.5 ccw(c-2637.5,1037.5) -2612.5,1037.5 cw(c-2587.5,1037.5) -2587.5,1062.5 -2302.5,1062.5 ccw(c-2302.5,1077.5) -2287.5,1077.5 cw(c-2263.36,1077.5) -2280.43,1094.57 v1(-2280,1095)
  Bottom Layer w5: v1(-2280,1095) cw(c-2262.5,1095) -2262.5,1112.5 R553B.1@-2255.69,1112.5 -2255.69,1091.32 ccw(c-2231.39,1091.32) U101B.5@-2231.39,1067.03
ANALOG1.A8_P: P1.65 R577B.2 U101B.3 | length 1764.5
  Int6 (SB) w6: P1.65@-3202.3,187.5 -3175,187.5 -3163.71,187.5 ccw(c-3163.71,238.71) -3127.51,202.49 -3020.91,309.09 ccw(c-3059.32,347.5) -3005,347.5 -3005,856.74 cw(c-2849.24,856.74) -2849.24,1012.5 -2637.5,1012.5 ccw(c-2637.5,1037.5) -2612.5,1037.5 cw(c-2587.5,1037.5) -2587.5,1062.5 -2302.5,1062.5 ccw(c-2302.5,1077.5) -2287.5,1077.5 ccw(c-2311.64,1077.5) -2294.57,1094.57 v1(-2295,1095)
  Bottom Layer w5: U101B.3@-2343.6,1047.34 -2326.41,1047.34 ccw(c-2326.41,1056.25) -2317.5,1056.25 R577B.2@-2317.5,1110.59 ; R577B.2@-2319.41,1112.5 cw(c-2319.41,1110.59) R577B.2@-2317.5,1110.59 ; v1(-2295,1095) ccw(c-2310.59,1095) -2310.59,1110.59 R577B.2@-2317.5,1110.59
ANALOG2.A1_N: P1.62 R618C.1 U125C.5 | length 1417.7
  Int5 (ST) w6: P1.62@-3352.3,87.5 -3235.3,87.5 ccw(c-3202.3,87.5) -3169.3,87.5 -3163.71,87.5 ccw(c-3163.71,138.71) -3127.51,102.49 -3014.29,215.71 ccw(c-3085,286.42) -2985,286.42 -2985,690 cw(c-2850,690) -2850,825 -2690,825 ccw(c-2690,840) -2675,840 cw(c-2650.86,840) -2667.93,857.07 v1(-2667.5,857.5)
  Bottom Layer w5: v1(-2667.5,857.5) cw(c-2650,857.5) -2650,875 R618C.1@-2643.19,875 -2643.19,853.69 ccw(c-2618.89,853.69) U125C.5@-2618.89,829.4
ANALOG2.A1_P: P1.61 R634C.2 U125C.3 | length 1258.8
  Int6 (SB) w6: P1.61@-3202.3,87.5 -3163.71,87.5 ccw(c-3163.71,138.71) -3127.51,102.49 -3014.29,215.71 ccw(c-3085,286.42) -2985,286.42 -2985,689.26 cw(c-2849.26,689.26) -2849.26,825 -2690,825 ccw(c-2690,840) -2675,840 ccw(c-2699.14,840) -2682.07,857.07 v1(-2682.5,857.5)
  Bottom Layer w5: U125C.3@-2731.1,809.72 -2714.03,809.72 ccw(c-2714.03,818.75) -2705,818.75 -2705,873.19 ccw(c-2706.81,873.19) R634C.2@-2706.81,875 -2700,875 cw(c-2700,857.5) v1(-2682.5,857.5)
ANALOG2.A2_N: P1.60 R554C.1 U102C.5 | length 1905.4
  Int5 (ST) w6: P1.60@-3427.3,37.5 -3310.3,37.5 ccw(c-3277.3,37.5) -3244.3,37.5 -3163.7,37.5 ccw(c-3163.7,88.68) -3127.51,52.49 -2994.29,185.71 ccw(c-3065,256.42) -2965,256.42 -2965,660 cw(c-2850,660) -2850,775 -2637.5,775 ccw(c-2637.5,800) -2612.5,800 cw(c-2587.5,800) -2587.5,825 -2302.5,825 ccw(c-2302.5,840) -2287.5,840 cw(c-2263.36,840) -2280.43,857.07 v1(-2280,857.5)
  Bottom Layer w5: v1(-2280,857.5) cw(c-2262.5,857.5) -2262.5,875 R554C.1@-2255.69,875 -2255.69,853.82 ccw(c-2231.39,853.82) U102C.5@-2231.39,829.53
ANALOG2.A2_P: P1.59 R569C.2 U102C.3 | length 1746.8
  Int6 (SB) w6: P1.59@-3277.3,37.5 -3163.71,37.5 ccw(c-3163.71,88.71) -3127.51,52.49 -2994.29,185.71 ccw(c-3065,256.42) -2965,256.42 -2965,659.71 cw(c-2849.71,659.71) -2849.71,775 -2637.37,775 ccw(c-2637.37,799.87) -2612.5,799.87 -2612.5,800 cw(c-2587.5,800) -2587.5,825 -2302.5,825 ccw(c-2302.5,840) -2287.5,840 ccw(c-2311.64,840) -2294.57,857.07 v1(-2295,857.5)
  Bottom Layer w5: U102C.3@-2343.6,809.84 -2326.41,809.84 ccw(c-2326.41,818.75) -2317.5,818.75 -2317.5,873.19 ccw(c-2319.31,873.19) R569C.2@-2319.31,875 -2312.5,875 cw(c-2312.5,857.5) v1(-2295,857.5)
ANALOG2.A3_N: P1.58 R617C.1 U117C.5 | length 1298.8
  Int5 (ST) w6: P1.58@-3352.3,-12.5 -3235.3,-12.5 ccw(c-3202.3,-12.5) -3169.3,-12.5 -3163.7,-12.5 ccw(c-3163.7,38.68) -3127.51,2.49 -2974.29,155.71 ccw(c-3045,226.42) -2945,226.42 -2945,517.5 cw(c-2850,517.5) -2850,612.5 -2690,612.5 ccw(c-2690,627.5) -2675,627.5 cw(c-2650.86,627.5) -2667.93,644.57 v1(-2667.5,645)
  Bottom Layer w5: v1(-2667.5,645) cw(c-2650,645) -2650,662.5 R617C.1@-2643.19,662.5 -2643.19,641.32 ccw(c-2618.89,641.32) U117C.5@-2618.89,617.03
ANALOG2.A3_P: P1.57 R633C.2 U117C.3 | length 1139.7
  Int6 (SB) w6: P1.57@-3202.3,-12.5 -3163.71,-12.5 ccw(c-3163.71,38.71) -3127.51,2.49 -2974.29,155.71 ccw(c-3045,226.42) -2945,226.42 -2945,517.5 cw(c-2850,517.5) -2850,612.5 -2690,612.5 ccw(c-2690,627.5) -2675,627.5 ccw(c-2699.14,627.5) -2682.07,644.57 v1(-2682.5,645)
  Bottom Layer w5: U117C.3@-2731.1,597.34 -2713.91,597.34 ccw(c-2713.91,606.25) -2705,606.25 -2705,658.12 ccw(c-2711.19,658.12) R633C.2@-2706.81,662.5 -2700,662.5 cw(c-2700,645) v1(-2682.5,645)
ANALOG2.A4_N: P1.56 R553C.1 U101C.5 | length 1786.7
  Int5 (ST) w6: P1.56@-3427.3,-62.5 -3310.3,-62.5 ccw(c-3277.3,-62.5) -3244.3,-62.5 -3163.7,-62.5 ccw(c-3163.7,-11.32) -3127.51,-47.51 -2954.29,125.71 ccw(c-3025,196.42) -2925,196.42 -2925,487.5 cw(c-2850,487.5) -2850.17,562.5 -2637.5,562.5 ccw(c-2637.5,587.5) -2612.5,587.5 cw(c-2587.5,587.5) -2587.5,612.5 -2302.5,612.5 ccw(c-2302.5,627.5) -2287.5,627.5 cw(c-2263.36,627.5) -2280.43,644.57 v1(-2280,645)
  Bottom Layer w5: v1(-2280,645) cw(c-2262.5,645) -2262.5,662.5 R553C.1@-2255.69,662.5 -2255.69,641.32 ccw(c-2231.39,641.32) U101C.5@-2231.39,617.03
ANALOG2.A4_P: P1.55 R577C.2 U101C.3 | length 1625.3
  Int6 (SB) w6: P1.55@-3277.3,-62.5 -3207.5,-62.5 -3163.71,-62.5 ccw(c-3163.71,-11.29) -3127.51,-47.51 -2954.29,125.71 ccw(c-3025,196.42) -2925,196.42 -2925,487.5 cw(c-2850,487.5) -2850,562.5 -2637.5,562.5 ccw(c-2637.5,587.5) -2612.5,587.5 cw(c-2587.5,587.5) -2587.5,612.5 -2302.5,612.5 ccw(c-2302.5,627.5) -2287.5,627.5 ccw(c-2311.64,627.5) -2294.57,644.57 v1(-2295,645)
  Bottom Layer w5: U101C.3@-2343.6,597.34 -2326.41,597.34 ccw(c-2326.41,606.25) -2317.5,606.25 R577C.2@-2317.5,660.59 ; R577C.2@-2319.41,662.5 cw(c-2319.41,660.59) R577C.2@-2317.5,660.59 ; v1(-2295,645) ccw(c-2310.59,645) -2310.59,660.59 R577C.2@-2317.5,660.59
ANALOG2.A5_N: P1.54 R618D.1 U125D.5 | length 1155.1
  Int5 (ST) w6: P1.54@-3352.3,-112.5 -3235.3,-112.5 ccw(c-3202.3,-112.5) -3169.3,-112.5 -3163.7,-112.5 ccw(c-3163.7,-61.32) -3127.51,-97.51 -2934.29,95.71 ccw(c-3005,166.42) -2905,166.42 -2905,320 cw(c-2850,320) -2850,375 -2690,375 ccw(c-2690,390) -2675,390 cw(c-2650.86,390) -2667.93,407.07 v1(-2667.5,407.5)
  Bottom Layer w5: v1(-2667.5,407.5) cw(c-2650,407.5) -2650,425 R618D.1@-2643.19,425 -2643.19,403.69 ccw(c-2618.89,403.69) U125D.5@-2618.89,379.4
ANALOG2.A5_P: P1.53 R634D.2 U125D.3 | length 996.6
  Int6 (SB) w6: P1.53@-3202.3,-112.5 -3163.71,-112.5 ccw(c-3163.71,-61.29) -3127.51,-97.51 -2934.29,95.71 ccw(c-3005,166.42) -2905,166.42 -2905,320 cw(c-2850,320) -2850,375 -2690,375 ccw(c-2690,390) -2675,390 ccw(c-2699.14,390) -2682.07,407.07 v1(-2682.5,407.5)
  Bottom Layer w5: U125D.3@-2731.1,359.72 -2714.03,359.72 ccw(c-2714.03,368.75) -2705,368.75 -2705,423.19 ccw(c-2706.81,423.19) R634D.2@-2706.81,425 -2700,425 cw(c-2700,407.5) v1(-2682.5,407.5)
ANALOG2.A6_N: P1.52 R554D.1 U102D.5 | length 1642.9
  Int5 (ST) w6: P1.52@-3427.3,-162.5 -3310.3,-162.5 ccw(c-3277.3,-162.5) -3244.3,-162.5 -3163.71,-162.5 ccw(c-3163.71,-111.29) -3127.51,-147.51 -2914.29,65.71 ccw(c-2985,136.42) -2885,136.42 -2885,290 cw(c-2850,290) -2850,325 -2637.5,325 ccw(c-2637.5,350) -2612.5,350 cw(c-2587.5,350) -2587.5,375 -2302.5,375 ccw(c-2302.5,390) -2287.5,390 cw(c-2263.36,390) -2280.43,407.07 v1(-2280,407.5)
  Bottom Layer w5: v1(-2280,407.5) cw(c-2262.5,407.5) -2262.5,425 R554D.1@-2255.69,425 -2255.69,403.82 ccw(c-2231.39,403.82) U102D.5@-2231.39,379.53
ANALOG2.A6_P: P1.51 R569D.2 U102D.3 | length 1484.4
  Int6 (SB) w6: P1.51@-3277.3,-162.5 -3163.71,-162.5 ccw(c-3163.71,-111.29) -3127.51,-147.51 -2914.29,65.71 ccw(c-2985,136.42) -2885,136.42 -2885,290 cw(c-2850,290) -2850,325 -2637.37,325 ccw(c-2637.37,349.87) -2612.5,349.87 -2612.5,350 cw(c-2587.5,350) -2587.5,375 -2302.5,375 ccw(c-2302.5,390) -2287.5,390 ccw(c-2311.64,390) -2294.57,407.07 v1(-2295,407.5)
  Bottom Layer w5: U102D.3@-2343.6,359.84 -2326.41,359.84 ccw(c-2326.41,368.75) -2317.5,368.75 -2317.5,423.19 ccw(c-2319.31,423.19) R569D.2@-2319.31,425 -2312.5,425 cw(c-2312.5,407.5) v1(-2295,407.5)
ANALOG2.A7_N: P1.50 R617D.1 U117D.5 | length 1017.5
  Int5 (ST) w6: P1.50@-3352.3,-212.5 -3235.3,-212.5 ccw(c-3202.3,-212.5) -3169.3,-212.5 -3162.5,-212.5 ccw(c-3162.5,-164.22) -3128.36,-198.36 ; -3127.51,-197.51 -2894.29,35.71 ccw(c-2965,106.42) -2865,106.42 cw(c-2808.92,106.42) -2808.92,162.5 -2690,162.5 ccw(c-2690,177.5) -2675,177.5 cw(c-2650.86,177.5) -2667.93,194.57 v1(-2667.5,195)
  Bottom Layer w5: v1(-2667.5,195) cw(c-2650,195) -2650,212.5 R617D.1@-2643.19,212.5 -2643.19,191.32 ccw(c-2618.89,191.32) U117D.5@-2618.89,167.03
ANALOG2.A7_P: P1.49 R633D.2 U117D.3 | length 859.5
  Int6 (SB) w6: P1.49@-3202.3,-212.5 -3163.71,-212.5 ccw(c-3163.71,-161.29) -3127.51,-197.51 -2894.29,35.71 ccw(c-2965,106.42) -2865,106.42 cw(c-2808.92,106.42) -2808.92,162.5 -2690,162.5 ccw(c-2690,177.5) -2675,177.5 ccw(c-2699.14,177.5) -2682.07,194.57 v1(-2682.5,195)
  Bottom Layer w5: U117D.3@-2731.1,147.34 -2713.91,147.34 ccw(c-2713.91,156.25) -2705,156.25 -2705,208.12 ccw(c-2711.19,208.12) R633D.2@-2706.81,212.5 -2700,212.5 cw(c-2700,195) v1(-2682.5,195)
ANALOG2.A8_N: P1.48 R553D.1 U101D.5 | length 1506.5
  Int5 (ST) w6: P1.48@-3427.3,-262.5 -3310.3,-262.5 ccw(c-3277.3,-262.5) -3244.3,-262.5 -3180.18,-262.5 -3163.71,-262.5 ccw(c-3163.71,-211.29) -3127.51,-247.51 -2874.29,5.71 ccw(c-2945,76.42) -2845,76.42 cw(c-2808.92,76.42) -2808.92,112.5 -2637.5,112.5 ccw(c-2637.5,137.5) -2612.5,137.5 cw(c-2587.5,137.5) -2587.5,162.5 -2302.5,162.5 ccw(c-2302.5,177.5) -2287.5,177.5 cw(c-2263.36,177.5) -2280.43,194.57 v1(-2280,195)
  Bottom Layer w5: v1(-2280,195) cw(c-2262.5,195) -2262.5,212.5 R553D.1@-2255.69,212.5 -2255.69,191.32 ccw(c-2231.39,191.32) U101D.5@-2231.39,167.03
ANALOG2.A8_P: P1.47 R577D.2 U101D.3 | length 1402.5
  Int6 (SB) w6: P1.47@-3277.3,-262.5 -3180.18,-262.5 ; -3237.5,-262.5 -3180.18,-262.5 ; v1(-2295,195) -2294.57,194.57 cw(c-2311.64,177.5) -2287.5,177.5 cw(c-2302.5,177.5) -2302.5,162.5 -2587.5,162.5 ccw(c-2587.5,137.5) -2612.5,137.5 cw(c-2637.5,137.5) -2637.5,112.5 -2808.92,112.5 ccw(c-2808.92,76.42) -2845,76.42 cw(c-2945,76.42) -2874.29,5.71 -3127.5,-247.5 cw(c-3163.71,-211.29) -3163.71,-262.5 -3180.18,-262.5
  Bottom Layer w5: U101D.3@-2343.6,147.34 -2326.41,147.34 ccw(c-2326.41,156.25) -2317.5,156.25 R577D.2@-2317.5,210.59 ; R577D.2@-2319.41,212.5 cw(c-2319.41,210.59) R577D.2@-2317.5,210.59 ; v1(-2295,195) ccw(c-2310.59,195) -2310.59,210.59 R577D.2@-2317.5,210.59
ANALOG3.A1_N: P1.44 R618E.1 U125E.5 | length 1022.4
  Int5 (ST) w6: P1.44@-3427.3,-362.5 -3310.3,-362.5 ccw(c-3277.3,-362.5) -3244.3,-362.5 -3178.92,-362.5 ccw(c-3178.92,-262.5) -3108.21,-333.21 -2879.29,-104.29 cw(c-2808.58,-175) -2808.58,-75 -2690,-75 ccw(c-2690,-60) -2675,-60 cw(c-2650.86,-60) -2667.93,-42.93 v1(-2667.5,-42.5)
  Bottom Layer w5: v1(-2667.5,-42.5) cw(c-2650,-42.5) -2650,-25 R618E.1@-2643.19,-25 -2643.19,-46.31 ccw(c-2618.89,-46.31) U125E.5@-2618.89,-70.6
ANALOG3.A1_P: P1.43 R634E.2 U125E.3 | length 863.8
  Int6 (SB) w6: P1.43@-3277.3,-362.5 -3178.92,-362.5 ccw(c-3178.92,-262.5) -3108.21,-333.21 -2879.29,-104.29 cw(c-2808.58,-175) -2808.58,-75 -2690,-75 ccw(c-2690,-60) -2675,-60 ccw(c-2699.14,-60) -2682.07,-42.93 v1(-2682.5,-42.5)
  Bottom Layer w5: U125E.3@-2731.1,-90.28 -2714.03,-90.28 ccw(c-2714.03,-81.25) -2705,-81.25 -2705,-26.81 ccw(c-2706.81,-26.81) R634E.2@-2706.81,-25 -2700,-25 cw(c-2700,-42.5) v1(-2682.5,-42.5)
ANALOG3.A2_N: P1.42 R554E.1 U102E.5 | length 1363.3
  Int5 (ST) w6: P1.42@-3352.3,-412.5 -3235.3,-412.5 ccw(c-3202.3,-412.5) -3169.3,-412.5 -3151.42,-412.5 ccw(c-3151.42,-312.5) -3080.71,-383.21 -2851.79,-154.29 cw(c-2781.08,-225) -2781.08,-125 -2637.5,-125 ccw(c-2637.5,-100) -2612.5,-100 cw(c-2587.5,-100) -2587.5,-75 -2302.5,-75 ccw(c-2302.5,-60) -2287.5,-60 cw(c-2263.36,-60) -2280.43,-42.93 v1(-2280,-42.5)
  Bottom Layer w5: v1(-2280,-42.5) cw(c-2262.5,-42.5) -2262.5,-25 R554E.1@-2255.69,-25 -2255.69,-46.18 ccw(c-2231.39,-46.18) U102E.5@-2231.39,-70.47
ANALOG3.A2_P: P1.41 R569E.2 U102E.3 | length 1204.8
  Int6 (SB) w6: P1.41@-3202.3,-412.5 -3151.42,-412.5 ccw(c-3151.42,-312.5) -3080.71,-383.21 -2851.79,-154.29 cw(c-2781.08,-225) -2781.08,-125 -2637.37,-125 ccw(c-2637.37,-100.13) -2612.5,-100.13 -2612.5,-100 cw(c-2587.5,-100) -2587.5,-75 -2302.5,-75 ccw(c-2302.5,-60) -2287.5,-60 ccw(c-2311.64,-60) -2294.57,-42.93 v1(-2295,-42.5)
  Bottom Layer w5: U102E.3@-2343.6,-90.16 -2326.41,-90.16 ccw(c-2326.41,-81.25) -2317.5,-81.25 -2317.5,-26.81 ccw(c-2319.31,-26.81) R569E.2@-2319.31,-25 -2312.5,-25 cw(c-2312.5,-42.5) v1(-2295,-42.5)
ANALOG3.A3_N: P1.40 R617E.1 U117E.5 | length 975.6
  Int5 (ST) w6: P1.40@-3427.3,-462.5 -3310.3,-462.5 ccw(c-3277.3,-462.5) -3244.3,-462.5 -3142.78,-462.5 ccw(c-3142.78,-362.5) -3072.07,-433.21 -2955.65,-316.79 cw(c-2884.94,-387.5) -2884.94,-287.5 -2690,-287.5 ccw(c-2690,-272.5) -2675,-272.5 cw(c-2650.86,-272.5) -2667.93,-255.43 v1(-2667.5,-255)
  Bottom Layer w5: v1(-2667.5,-255) cw(c-2650,-255) -2650,-237.5 R617E.1@-2643.19,-237.5 -2643.19,-258.68 ccw(c-2618.89,-258.68) U117E.5@-2618.89,-282.97
ANALOG3.A3_P: P1.39 R633E.2 U117E.3 | length 816.5
  Int6 (SB) w6: P1.39@-3277.3,-462.5 -3142.78,-462.5 ccw(c-3142.78,-362.5) -3072.07,-433.21 -2955.65,-316.79 cw(c-2884.94,-387.5) -2884.94,-287.5 -2690,-287.5 ccw(c-2690,-272.5) -2675,-272.5 ccw(c-2699.14,-272.5) -2682.07,-255.43 v1(-2682.5,-255)
  Bottom Layer w5: U117E.3@-2731.1,-302.66 -2713.91,-302.66 ccw(c-2713.91,-293.75) -2705,-293.75 -2705,-241.88 ccw(c-2711.19,-241.88) R633E.2@-2706.81,-237.5 -2700,-237.5 cw(c-2700,-255) v1(-2682.5,-255)
ANALOG3.A4_N: P1.38 R553E.1 U101E.5 | length 1316.7
  Int5 (ST) w6: P1.38@-3352.3,-512.5 -3235.3,-512.5 ccw(c-3202.3,-512.5) -3169.3,-512.5 -3124.1,-512.5 ccw(c-3124.1,-412.5) -3053.39,-483.21 -2936.97,-366.79 cw(c-2866.26,-437.5) -2866.26,-337.5 -2637.5,-337.5 ccw(c-2637.5,-312.5) -2612.5,-312.5 cw(c-2587.5,-312.5) -2587.5,-287.5 -2302.5,-287.5 ccw(c-2302.5,-272.5) -2287.5,-272.5 cw(c-2263.36,-272.5) -2280.43,-255.43 v1(-2280,-255)
  Bottom Layer w5: v1(-2280,-255) cw(c-2262.5,-255) -2262.5,-237.5 R553E.1@-2255.69,-237.5 -2255.69,-258.68 ccw(c-2231.39,-258.68) U101E.5@-2231.39,-282.97
ANALOG3.A4_P: P1.37 R577E.2 U101E.3 | length 1155.3
  Int6 (SB) w6: P1.37@-3202.3,-512.5 -3124.1,-512.5 ccw(c-3124.1,-412.5) -3053.39,-483.21 -2936.97,-366.79 cw(c-2866.26,-437.5) -2866.26,-337.5 -2637.5,-337.5 ccw(c-2637.5,-312.5) -2612.5,-312.5 cw(c-2587.5,-312.5) -2587.5,-287.5 -2302.5,-287.5 ccw(c-2302.5,-272.5) -2287.5,-272.5 ccw(c-2311.64,-272.5) -2294.57,-255.43 v1(-2295,-255)
  Bottom Layer w5: U101E.3@-2343.6,-302.66 -2326.41,-302.66 ccw(c-2326.41,-293.75) -2317.5,-293.75 R577E.2@-2317.5,-239.41 ; R577E.2@-2319.41,-237.5 cw(c-2319.41,-239.41) R577E.2@-2317.5,-239.41 ; v1(-2295,-255) ccw(c-2310.59,-255) -2310.59,-239.41 R577E.2@-2317.5,-239.41
ANALOG3.A5_N: P1.36 R618F.1 U125F.5 | length 921.9
  Int5 (ST) w6: P1.36@-3427.3,-562.5 -3310.3,-562.5 ccw(c-3277.3,-562.5) -3244.3,-562.5 -3067.68,-562.5 ccw(c-3067.68,-502.14) -3025,-544.82 cw(c-2977.14,-592.68) -2977.14,-525 -2690,-525 ccw(c-2690,-510) -2675,-510 cw(c-2650.86,-510) -2667.93,-492.93 v1(-2667.5,-492.5)
  Bottom Layer w5: v1(-2667.5,-492.5) cw(c-2650,-492.5) -2650,-475 R618F.1@-2643.19,-475 -2643.19,-496.31 ccw(c-2618.89,-496.31) U125F.5@-2618.89,-520.6
ANALOG3.A5_P: P1.35 R634F.2 U125F.3 | length 763.3
  Int6 (SB) w6: P1.35@-3277.3,-562.5 -3067.68,-562.5 ccw(c-3067.68,-502.14) -3025,-544.82 cw(c-2977.14,-592.68) -2977.14,-525 -2690,-525 ccw(c-2690,-510) -2675,-510 ccw(c-2699.14,-510) -2682.07,-492.93 v1(-2682.5,-492.5)
  Bottom Layer w5: U125F.3@-2731.1,-540.28 -2714.03,-540.28 ccw(c-2714.03,-531.25) -2705,-531.25 -2705,-476.81 ccw(c-2706.81,-476.81) R634F.2@-2706.81,-475 -2700,-475 cw(c-2700,-492.5) v1(-2682.5,-492.5)
ANALOG3.A6_N: P1.34 R554F.1 U102F.5 | length 1262.8
  Int5 (ST) w6: P1.34@-3352.3,-612.5 -3235.3,-612.5 ccw(c-3202.3,-612.5) -3169.3,-612.5 -3067.68,-612.5 ccw(c-3067.68,-552.14) -3025,-594.82 cw(c-2977.14,-642.68) -2977.14,-575 -2637.5,-575 ccw(c-2637.5,-550) -2612.5,-550 cw(c-2587.5,-550) -2587.5,-525 -2302.5,-525 ccw(c-2302.5,-510) -2287.5,-510 cw(c-2263.36,-510) -2280.43,-492.93 v1(-2280,-492.5)
  Bottom Layer w5: v1(-2280,-492.5) cw(c-2262.5,-492.5) -2262.5,-475 R554F.1@-2255.69,-475 -2255.69,-496.18 ccw(c-2231.39,-496.18) U102F.5@-2231.39,-520.47
ANALOG3.A6_P: P1.33 R569F.2 U102F.3 | length 1104.3
  Int6 (SB) w6: P1.33@-3202.3,-612.5 -3067.68,-612.5 ccw(c-3067.68,-552.14) -3025,-594.82 cw(c-2977.14,-642.68) -2977.14,-575 -2637.37,-575 ccw(c-2637.37,-550.13) -2612.5,-550 cw(c-2587.5,-550) -2587.5,-525 -2302.5,-525 ccw(c-2302.5,-510) -2287.5,-510 ccw(c-2311.64,-510) -2294.57,-492.93 v1(-2295,-492.5)
  Bottom Layer w5: U102F.3@-2343.6,-540.16 -2326.41,-540.16 ccw(c-2326.41,-531.25) -2317.5,-531.25 -2317.5,-476.81 ccw(c-2319.31,-476.81) R569F.2@-2319.31,-475 -2312.5,-475 cw(c-2312.5,-492.5) v1(-2295,-492.5)
ANALOG3.A7_N: P1.32 R617F.1 U117F.5 | length 934.2
  Int5 (ST) w6: P1.32@-3427.3,-662.5 -3310.3,-662.5 ccw(c-3277.3,-662.5) -3244.3,-662.5 -3069.35,-662.5 cw(c-3069.35,-762.5) -2998.64,-691.79 -2982.22,-708.21 ccw(c-2911.51,-637.5) -2911.51,-737.5 -2690,-737.5 ccw(c-2690,-722.5) -2675,-722.5 cw(c-2650.86,-722.5) -2667.93,-705.43 v1(-2667.5,-705)
  Bottom Layer w5: v1(-2667.5,-705) cw(c-2650,-705) -2650,-687.5 R617F.1@-2643.19,-687.5 -2643.19,-708.68 ccw(c-2618.89,-708.68) U117F.5@-2618.89,-732.97
ANALOG3.A7_P: P1.31 R633F.2 U117F.3 | length 775.1
  Int6 (SB) w6: P1.31@-3277.3,-662.5 -3069.35,-662.5 cw(c-3069.35,-762.5) -2998.64,-691.79 -2982.22,-708.21 ccw(c-2911.51,-637.5) -2911.51,-737.5 -2690,-737.5 ccw(c-2690,-722.5) -2675,-722.5 ccw(c-2699.14,-722.5) -2682.07,-705.43 v1(-2682.5,-705)
  Bottom Layer w5: U117F.3@-2731.1,-752.66 -2713.91,-752.66 ccw(c-2713.91,-743.75) -2705,-743.75 -2705,-691.88 ccw(c-2711.19,-691.88) R633F.2@-2706.81,-687.5 -2700,-687.5 cw(c-2700,-705) v1(-2682.5,-705)
ANALOG3.A8_N: P1.30 R553F.1 U101F.5 | length 1275.9
  Int5 (ST) w6: P1.30@-3352.3,-712.5 -3235.3,-712.5 ccw(c-3202.3,-712.5) -3169.3,-712.5 -3076.42,-712.5 cw(c-3076.42,-812.5) -3005.71,-741.79 -2985,-762.5 ccw(c-2924.64,-702.14) -2924.64,-787.5 -2637.5,-787.5 ccw(c-2637.5,-762.5) -2612.5,-762.5 cw(c-2587.5,-762.5) -2587.5,-737.5 -2302.5,-737.5 ccw(c-2302.5,-722.5) -2287.5,-722.5 cw(c-2263.36,-722.5) -2280.43,-705.43 v1(-2280,-705)
  Bottom Layer w5: v1(-2280,-705) cw(c-2262.5,-705) -2262.5,-687.5 R553F.1@-2255.69,-687.5 -2255.69,-708.68 ccw(c-2231.39,-708.68) U101F.5@-2231.39,-732.97
ANALOG3.A8_P: P1.29 R577F.2 U101F.3 | length 1114.5
  Int6 (SB) w6: P1.29@-3202.3,-712.5 -3076.42,-712.5 cw(c-3076.42,-812.5) -3005.71,-741.79 -2985,-762.5 ccw(c-2924.65,-702.15) -2924.65,-787.5 -2637.5,-787.5 ccw(c-2637.5,-762.5) -2612.5,-762.5 cw(c-2587.5,-762.5) -2587.5,-737.5 -2302.5,-737.5 ccw(c-2302.5,-722.5) -2287.5,-722.5 ccw(c-2311.64,-722.5) -2294.57,-705.43 v1(-2295,-705)
  Bottom Layer w5: U101F.3@-2343.6,-752.66 -2326.41,-752.66 ccw(c-2326.41,-743.75) -2317.5,-743.75 R577F.2@-2317.5,-689.41 ; R577F.2@-2319.41,-687.5 cw(c-2319.41,-689.41) R577F.2@-2317.5,-689.41 ; v1(-2295,-705) ccw(c-2310.59,-705) -2310.59,-689.41 R577F.2@-2317.5,-689.41
ANALOG4.A1_N: P1.26 R618G.1 U125G.5 | length 896.5
  Int5 (ST) w6: P1.26@-3352.3,-812.5 -3235.3,-812.5 ccw(c-3202.3,-812.5) -3169.3,-812.5 -3086.6,-812.5 cw(c-3086.6,-892.98) -3029.69,-836.07 -2919.59,-946.18 ccw(c-2850,-876.59) -2850,-975 -2690,-975 ccw(c-2690,-960) -2675,-960 cw(c-2650.86,-960) -2667.93,-942.93 v1(-2667.5,-942.5)
  Bottom Layer w5: v1(-2667.5,-942.5) cw(c-2650,-942.5) -2650,-925 R618G.1@-2643.19,-925 -2643.19,-946.31 ccw(c-2618.89,-946.31) U125G.5@-2618.89,-970.6
ANALOG4.A1_P: P1.25 R634G.2 U125G.3 | length 737.9
  Int6 (SB) w6: P1.25@-3202.3,-812.5 -3086.6,-812.5 cw(c-3086.6,-892.98) -3029.69,-836.07 -2919.59,-946.18 ccw(c-2850,-876.59) -2850,-975 -2690,-975 ccw(c-2690,-960) -2675,-960 ccw(c-2699.14,-960) -2682.07,-942.93 v1(-2682.5,-942.5)
  Bottom Layer w5: U125G.3@-2731.1,-990.28 -2714.03,-990.28 ccw(c-2714.03,-981.25) -2705,-981.25 -2705,-926.81 ccw(c-2706.81,-926.81) R634G.2@-2706.81,-925 -2700,-925 cw(c-2700,-942.5) v1(-2682.5,-942.5)
ANALOG4.A2_N: P1.24 R554G.1 U102G.5 | length 1388.3
  Int5 (ST) w6: P1.24@-3427.3,-862.5 -3310.3,-862.5 ccw(c-3277.3,-862.5) -3244.3,-862.5 -3165.41,-862.5 ; -3165,-862.5 -3074.1,-862.5 cw(c-3074.1,-933.71) -3023.74,-883.36 -2904.8,-1002.3 ccw(c-2850,-947.5) -2850,-1025 -2637.5,-1025 ccw(c-2637.5,-1000) -2612.5,-1000 cw(c-2587.5,-1000) -2587.5,-975 -2302.5,-975 ccw(c-2302.5,-960) -2287.5,-960 cw(c-2263.36,-960) -2280.43,-942.93 v1(-2280,-942.5)
  Bottom Layer w5: v1(-2280,-942.5) cw(c-2262.5,-942.5) -2262.5,-925 R554G.1@-2255.69,-925 -2255.69,-946.18 ccw(c-2231.39,-946.18) U102G.5@-2231.39,-970.47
